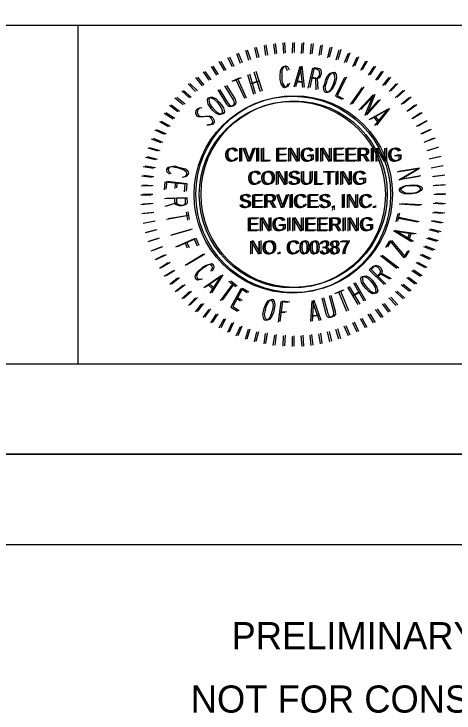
# Model space of a CAD drawing. Extents: x -16 to 5016, y -5 to 5003.
# Drawn here: x 23.858 to 26.289, y -3.799 to 0.062 of the extents above; entities that cross this region are included whole.
import ezdxf

# ---------------------------------------------------------------- set-up
doc = ezdxf.new("R2010")
doc.units = 0
for name, color, linetype in [('Level 8', 7, 'Continuous'), ('RD_SHT_Bndy', 7, 'Continuous'), ('RD_SHT_IplotShp', 7, 'Continuous'), ('RD_SHT_Misc1', 7, 'Continuous'), ('RD_SHT_SEAL_DR', 7, 'Continuous'), ('RD_SHT_SEAL_MA', 7, 'Continuous'), ('RD_SHT_Snap', 7, 'Continuous'), ('RD_SHT_TX', 7, 'Continuous')]:
    doc.layers.add(name, color=color, linetype=linetype)

msp = doc.modelspace()

# ---------------------------------------------------------------- linework, layer by layer
at = {"layer": 'RD_SHT_Bndy'}
for p, q in [((0, -1.87), (33.5, -1.87)), ((33.771, -2.37), (-1.429, -2.37)), ((33.77, -2.871), (-1.43, -2.87))]:
    msp.add_line(p, q, dxfattribs=at)
at = {"layer": 'RD_SHT_IplotShp'}
msp.add_lwpolyline([(-2.129, 19.63), (33.871, 19.63), (33.871, -2.37), (-2.129, -2.37)], close=True, dxfattribs=at)
at = {"layer": 'RD_SHT_Misc1'}
msp.add_lwpolyline([(33.7703, -2.37), (33.771, 19.63), (-0.229, 19.631), (-0.2297, -2.369)], close=True, dxfattribs=at)
at = {"layer": 'RD_SHT_SEAL_DR'}
for p, q in [((25.2492, -0.1087), (25.2582, -0.1647)), ((25.3012, -0.1017), (25.3082, -0.1567)), ((25.3532, -0.0947), (25.3562, -0.1527)), ((25.4062, -0.0947), (25.4052, -0.1507)), ((25.4582, -0.0957), (25.4542, -0.1537)), ((25.5102, -0.1007), (25.5032, -0.1577)), ((25.5612, -0.1087), (25.5522, -0.1637)), ((25.0972, -0.1527), (25.1182, -0.2067)), ((25.1462, -0.1357), (25.1642, -0.1897)), ((25.1962, -0.1207), (25.2102, -0.1767)), ((25.6132, -0.1207), (25.5992, -0.1767)), ((25.6632, -0.1347), (25.6462, -0.1907)), ((25.7132, -0.1527), (25.6922, -0.2057)), ((25.0482, -0.1747), (25.0732, -0.2257)), ((25.7612, -0.1747), (25.7382, -0.2267)), ((24.9572, -0.2257), (24.9862, -0.2727)), ((25.0002, -0.1977), (25.0292, -0.2477)), ((25.8092, -0.1977), (25.7812, -0.2467)), ((25.8552, -0.2257), (25.8242, -0.2737)), ((24.9122, -0.2547), (24.9452, -0.3007)), ((25.8972, -0.2537), (25.8642, -0.3007)), ((24.8712, -0.2867), (24.9072, -0.3317)), ((25.9382, -0.2867), (25.9042, -0.3307)), ((24.8302, -0.3217), (24.8712, -0.3627)), ((25.9792, -0.3217), (25.9402, -0.3627)), ((24.7952, -0.3597), (24.8372, -0.3977)), ((26.0172, -0.3587), (25.9742, -0.3977)), ((24.7572, -0.3977), (24.8032, -0.4347)), ((26.0512, -0.3977), (26.0072, -0.4347)), ((24.7272, -0.4397), (24.7732, -0.4747)), ((26.0832, -0.4397), (26.0372, -0.4737)), ((24.6972, -0.4827), (24.7472, -0.5137)), ((26.1132, -0.4837), (26.0652, -0.5137)), ((24.6712, -0.5297), (24.7202, -0.5567)), ((26.1412, -0.5287), (26.0902, -0.5567)), ((24.6462, -0.5757), (24.6982, -0.5997)), ((26.1622, -0.5757), (26.1132, -0.5997)), ((24.6262, -0.6247), (24.6792, -0.6457)), ((26.1842, -0.6237), (26.1312, -0.6447)), ((24.6072, -0.6747), (24.6632, -0.6917)), ((26.2032, -0.6737), (26.1482, -0.6917)), ((24.5942, -0.7257), (24.6492, -0.7397)), ((26.2172, -0.7247), (26.1612, -0.7377)), ((24.5822, -0.7767), (24.6392, -0.7867)), ((26.2282, -0.7757), (26.1722, -0.7877)), ((24.5732, -0.8287), (24.6312, -0.8357)), ((26.2382, -0.8277), (26.1792, -0.8347)), ((24.5702, -0.8817), (24.6262, -0.8847)), ((26.2422, -0.8807), (26.1842, -0.8847)), ((24.5692, -0.9337), (24.6252, -0.9337)), ((26.2432, -0.9337), (26.1872, -0.9327)), ((24.5692, -0.9867), (24.6262, -0.9827)), ((26.2422, -0.9857), (26.1842, -0.9817)), ((24.5742, -1.0377), (24.6312, -1.0317)), ((26.2372, -1.0377), (26.1792, -1.0327)), ((24.5812, -1.0907), (24.6372, -1.0797)), ((26.2282, -1.0907), (26.1722, -1.0797)), ((24.5942, -1.1427), (24.6482, -1.1277)), ((26.2172, -1.1417), (26.1612, -1.1267)), ((24.6092, -1.1917), (24.6622, -1.1747)), ((26.2032, -1.1917), (26.1482, -1.1747)), ((24.6262, -1.2427), (24.6802, -1.2217)), ((26.1842, -1.2407), (26.1312, -1.2207)), ((24.6472, -1.2917), (24.7002, -1.2657)), ((26.1632, -1.2907), (26.1122, -1.2657)), ((24.6712, -1.3387), (24.7202, -1.3087)), ((26.1402, -1.3377), (26.0892, -1.3097)), ((24.6982, -1.3827), (24.7462, -1.3537)), ((26.1132, -1.3847), (26.0652, -1.3537)), ((24.7282, -1.4277), (24.7722, -1.3927)), ((26.0832, -1.4277), (26.0372, -1.3927)), ((24.7582, -1.4677), (24.8032, -1.4327)), ((26.0522, -1.4677), (26.0072, -1.4317)), ((24.7952, -1.5077), (24.8382, -1.4687)), ((24.8322, -1.5447), (24.8712, -1.5037)), ((25.9792, -1.5447), (25.9392, -1.5027)), ((26.0172, -1.5077), (25.9752, -1.4687)), ((24.8712, -1.5807), (24.9062, -1.5367)), ((25.9382, -1.5817), (25.9042, -1.5367)), ((24.9132, -1.6117), (24.9462, -1.5667)), ((25.8982, -1.6117), (25.8652, -1.5667)), ((24.9552, -1.6417), (24.9862, -1.5937)), ((25.0022, -1.6687), (25.0292, -1.6197)), ((25.8092, -1.6687), (25.7812, -1.6197)), ((25.8542, -1.6417), (25.8252, -1.5937)), ((25.0492, -1.6927), (25.0732, -1.6407)), ((25.7152, -1.7127), (25.6922, -1.6597)), ((25.7632, -1.6917), (25.7392, -1.6407)), ((25.0962, -1.7137), (25.1192, -1.6607)), ((25.1462, -1.7317), (25.1632, -1.6767)), ((25.1962, -1.7457), (25.2102, -1.6907)), ((25.6132, -1.7457), (25.6002, -1.6907)), ((25.6632, -1.7317), (25.6462, -1.6777)), ((25.2492, -1.7577), (25.2582, -1.6997)), ((25.3002, -1.7667), (25.3082, -1.7087)), ((25.3542, -1.7707), (25.3572, -1.7127)), ((25.4062, -1.7717), (25.4062, -1.7157)), ((25.4592, -1.7717), (25.4552, -1.7127)), ((25.5102, -1.7667), (25.5032, -1.7087)), ((25.5612, -1.7577), (25.5522, -1.7017))]:
    msp.add_line(p, q, dxfattribs=at)
for points in [[(25.3792, -0.2487), (25.3702, -0.2297), (25.3612, -0.2267), (25.3562, -0.2267), (25.3472, -0.2307), (25.3382, -0.2497), (25.3372, -0.2757), (25.3372, -0.2887), (25.3372, -0.2977), (25.3382, -0.3047), (25.3412, -0.3207), (25.3522, -0.3377), (25.3602, -0.3407), (25.3642, -0.3407), (25.3732, -0.3367), (25.3822, -0.3187)], [(25.4152, -0.3377), (25.4482, -0.2257), (25.4612, -0.3417)], [(25.1582, -0.2687), (25.1912, -0.3777)], [(25.2302, -0.3647), (25.1952, -0.2557)], [(25.4932, -0.3447), (25.5182, -0.2337), (25.5452, -0.2397), (25.5522, -0.2457), (25.5552, -0.2637), (25.5532, -0.2757), (25.5432, -0.2917), (25.5342, -0.2937), (25.5052, -0.2887)], [(25.6262, -0.2597), (25.6312, -0.2617), (25.6372, -0.2717), (25.6402, -0.2927), (25.6342, -0.3137), (25.6272, -0.3337), (25.6162, -0.3537), (25.6012, -0.3687), (25.5912, -0.3697), (25.5872, -0.3677), (25.5812, -0.3607), (25.5772, -0.3397), (25.5842, -0.3187), (25.5902, -0.2977), (25.6002, -0.2777), (25.6152, -0.2617), (25.6262, -0.2597)], [(25.0732, -0.3067), (25.1142, -0.2887)], [(25.0942, -0.2977), (25.1412, -0.4007)], [(25.2122, -0.3087), (25.1752, -0.3217)], [(25.5332, -0.2937), (25.5362, -0.3537)], [(25.6942, -0.2867), (25.6432, -0.3887), (25.6782, -0.4057)], [(24.9932, -0.3547), (25.0412, -0.4327), (25.0522, -0.4447), (25.0662, -0.4457), (25.0822, -0.4367), (25.0852, -0.4257), (25.0812, -0.4087), (25.0332, -0.3327)], [(25.4592, -0.3137), (25.4222, -0.3097)], [(25.7272, -0.4347), (25.7932, -0.3407)], [(25.7732, -0.4657), (25.8512, -0.3817), (25.8062, -0.4957), (25.8822, -0.4107)], [(24.9392, -0.4007), (24.9432, -0.3977), (24.9542, -0.3967), (24.9742, -0.4057), (24.9902, -0.4227), (25.0022, -0.4377), (25.0152, -0.4567), (25.0202, -0.4777), (25.0152, -0.4867), (25.0112, -0.4897), (25.0022, -0.4917), (24.9832, -0.4837), (24.9672, -0.4687), (24.9532, -0.4517), (24.9402, -0.4327), (24.9362, -0.4107), (24.9392, -0.4007)], [(24.8952, -0.4557), (24.8812, -0.4587), (24.8722, -0.4687), (24.8702, -0.4827), (24.8762, -0.4957), (24.8812, -0.4997), (24.8952, -0.5037), (24.9362, -0.4997), (24.9492, -0.5037), (24.9572, -0.5117), (24.9642, -0.5267), (24.9632, -0.5377), (24.9542, -0.5477), (24.9462, -0.5497), (24.9342, -0.5487)], [(25.8302, -0.5177), (25.9322, -0.4607), (25.8602, -0.5517)], [(25.8772, -0.5307), (25.8552, -0.5037)], [(24.7962, -0.8367), (24.8152, -0.8327), (24.8212, -0.8247), (24.8232, -0.8187), (24.8212, -0.8087), (24.8052, -0.7957), (24.7822, -0.7887), (24.7672, -0.7857), (24.7582, -0.7827), (24.7522, -0.7807), (24.7372, -0.7797), (24.7172, -0.7837), (24.7112, -0.7917), (24.7102, -0.7967), (24.7112, -0.8057), (24.7272, -0.8207)], [(26.1052, -0.8327), (25.9932, -0.8517), (26.0982, -0.7897), (25.9842, -0.8087)], [(24.8102, -0.9167), (24.8142, -0.8757), (24.7022, -0.8637), (24.6972, -0.9057)], [(24.7582, -0.8707), (24.7562, -0.8987)], [(25.9972, -0.9107), (25.9972, -0.9047), (26.0032, -0.8957), (26.0222, -0.8857), (26.0432, -0.8827), (26.0652, -0.8817), (26.0872, -0.8827), (26.1062, -0.8907), (26.1122, -0.8987), (26.1122, -0.9037), (26.1072, -0.9127), (26.0892, -0.9247), (26.0662, -0.9277), (26.0462, -0.9287), (26.0232, -0.9277), (26.0042, -0.9187), (25.9972, -0.9107)], [(24.7002, -0.9547), (24.8132, -0.9507), (24.8142, -0.9807), (24.8102, -0.9887), (24.7932, -0.9957), (24.7822, -0.9957), (24.7632, -0.9897), (24.7572, -0.9817), (24.7572, -0.9537)], [(24.7572, -0.9817), (24.7012, -0.9987)], [(26.1112, -0.9927), (25.9962, -0.9857)], [(24.8192, -1.0297), (24.8262, -1.0737)], [(25.9792, -1.0827), (25.9892, -1.0377)], [(24.8232, -1.0507), (24.7102, -1.0697)], [(25.9842, -1.0607), (26.0962, -1.0837)], [(24.7342, -1.1567), (24.8442, -1.1247)], [(26.0642, -1.1937), (25.9642, -1.1337), (26.0792, -1.1497)], [(26.0522, -1.1467), (26.0402, -1.1797)], [(24.8812, -1.2167), (24.8642, -1.1777), (24.7602, -1.2237)], [(25.9222, -1.2247), (25.9432, -1.1887), (26.0212, -1.2817), (26.0432, -1.2437)], [(24.8132, -1.2007), (24.8252, -1.2277)], [(24.8132, -1.3217), (24.9122, -1.2627)], [(25.9832, -1.3417), (25.8922, -1.2717)], [(24.9552, -1.3557), (24.9642, -1.3377), (24.9622, -1.3277), (24.9582, -1.3237), (24.9502, -1.3187), (24.9302, -1.3237), (24.9082, -1.3377), (24.8982, -1.3457), (24.8902, -1.3517), (24.8852, -1.3557), (24.8742, -1.3677), (24.8662, -1.3857), (24.8692, -1.3947), (24.8722, -1.3987), (24.8812, -1.4027), (24.9002, -1.4007)], [(25.9122, -1.4297), (25.8302, -1.3487), (25.8512, -1.3287), (25.8592, -1.3257), (25.8772, -1.3327), (25.8842, -1.3407), (25.8922, -1.3577), (25.8892, -1.3687), (25.8702, -1.3877)], [(24.9162, -1.4457), (25.0122, -1.3787), (24.9492, -1.4777)], [(25.7862, -1.3887), (25.7922, -1.3857), (25.8032, -1.3847), (25.8222, -1.3937), (25.8372, -1.4087), (25.8512, -1.4277), (25.8622, -1.4467), (25.8672, -1.4667), (25.8622, -1.4757), (25.8582, -1.4797), (25.8482, -1.4807), (25.8292, -1.4707), (25.8142, -1.4537), (25.8012, -1.4387), (25.7872, -1.4187), (25.7842, -1.3987), (25.7862, -1.3887)], [(25.8882, -1.3687), (25.9422, -1.3987)], [(25.0742, -1.4267), (25.0072, -1.5187)], [(25.0552, -1.4117), (25.0912, -1.4397)], [(25.8022, -1.5217), (25.7452, -1.4227)], [(24.9642, -1.4527), (24.9382, -1.4297)], [(25.1562, -1.4747), (25.1212, -1.4537), (25.0662, -1.5537), (25.1022, -1.5757)], [(25.6402, -1.4787), (25.6822, -1.4607)], [(25.7102, -1.4437), (25.7682, -1.5407)], [(25.0932, -1.5037), (25.1192, -1.5187)], [(25.5682, -1.5047), (25.5912, -1.5917), (25.5982, -1.6067), (25.6092, -1.6117), (25.6282, -1.6057), (25.6352, -1.5967), (25.6342, -1.5817), (25.6102, -1.4927)], [(25.6612, -1.4697), (25.7052, -1.5757)], [(25.7732, -1.4717), (25.7392, -1.4917)], [(25.2822, -1.5137), (25.2882, -1.5157), (25.2962, -1.5247), (25.2992, -1.5437), (25.2962, -1.5677), (25.2912, -1.5867), (25.2822, -1.6077), (25.2692, -1.6257), (25.2602, -1.6277), (25.2542, -1.6267), (25.2482, -1.6197), (25.2422, -1.5977), (25.2472, -1.5757), (25.2512, -1.5557), (25.2602, -1.5347), (25.2722, -1.5187), (25.2822, -1.5137)], [(25.3812, -1.5287), (25.3422, -1.5247), (25.3272, -1.6367)], [(25.5072, -1.6337), (25.5152, -1.5187), (25.5532, -1.6287)], [(25.3352, -1.5807), (25.3632, -1.5837)], [(25.5442, -1.6017), (25.5102, -1.6057)]]:
    msp.add_lwpolyline(points, dxfattribs=at)
for major_axis in [(0, 0.5436), (0, 0.515)]:
    msp.add_ellipse((25.4055, -0.9331), major_axis=major_axis, ratio=0.998589, dxfattribs=at)
at = {"layer": 'RD_SHT_SEAL_MA'}
for p, q in [((25.2393, -0.1114), (25.2483, -0.1674)), ((25.2913, -0.1044), (25.2983, -0.1594)), ((25.3433, -0.0974), (25.3463, -0.1554)), ((25.3963, -0.0974), (25.3953, -0.1534)), ((25.4483, -0.0984), (25.4443, -0.1564)), ((25.5003, -0.1034), (25.4933, -0.1604)), ((25.5513, -0.1114), (25.5423, -0.1664)), ((25.1363, -0.1384), (25.1543, -0.1924)), ((25.1863, -0.1234), (25.2003, -0.1794)), ((25.6033, -0.1234), (25.5893, -0.1794)), ((25.6533, -0.1374), (25.6363, -0.1934)), ((25.0383, -0.1774), (25.0633, -0.2284)), ((25.0873, -0.1554), (25.1083, -0.2094)), ((25.7033, -0.1554), (25.6823, -0.2084)), ((25.7513, -0.1774), (25.7283, -0.2294)), ((24.9473, -0.2284), (24.9763, -0.2754)), ((24.9903, -0.2004), (25.0193, -0.2504)), ((25.7993, -0.2004), (25.7713, -0.2494)), ((25.8453, -0.2284), (25.8143, -0.2764)), ((24.9023, -0.2574), (24.9353, -0.3034)), ((25.8873, -0.2564), (25.8543, -0.3034)), ((24.8613, -0.2894), (24.8973, -0.3344)), ((25.9283, -0.2894), (25.8943, -0.3334)), ((24.8203, -0.3244), (24.8613, -0.3654)), ((25.9693, -0.3244), (25.9303, -0.3654)), ((24.7853, -0.3624), (24.8273, -0.4004)), ((26.0073, -0.3614), (25.9643, -0.4004)), ((24.7473, -0.4004), (24.7933, -0.4374)), ((26.0413, -0.4004), (25.9973, -0.4374)), ((24.7173, -0.4424), (24.7633, -0.4774)), ((26.0733, -0.4424), (26.0273, -0.4764)), ((24.6873, -0.4854), (24.7373, -0.5164)), ((26.1033, -0.4864), (26.0553, -0.5164)), ((24.6613, -0.5324), (24.7103, -0.5594)), ((26.1313, -0.5314), (26.0803, -0.5594)), ((24.6363, -0.5784), (24.6883, -0.6024)), ((26.1523, -0.5784), (26.1033, -0.6024)), ((24.6163, -0.6274), (24.6693, -0.6484)), ((26.1743, -0.6264), (26.1213, -0.6474)), ((24.5973, -0.6774), (24.6533, -0.6944)), ((26.1933, -0.6764), (26.1383, -0.6944)), ((24.5843, -0.7284), (24.6393, -0.7424)), ((26.2073, -0.7274), (26.1513, -0.7404)), ((24.5723, -0.7794), (24.6293, -0.7894)), ((26.2183, -0.7784), (26.1623, -0.7904)), ((24.5633, -0.8314), (24.6213, -0.8384)), ((26.2283, -0.8304), (26.1693, -0.8374)), ((24.5603, -0.8844), (24.6163, -0.8874)), ((26.2323, -0.8834), (26.1743, -0.8874)), ((24.5593, -0.9364), (24.6153, -0.9364)), ((26.2333, -0.9364), (26.1773, -0.9354)), ((24.5593, -0.9894), (24.6163, -0.9854)), ((26.2323, -0.9884), (26.1743, -0.9844)), ((24.5643, -1.0404), (24.6213, -1.0344)), ((26.2273, -1.0404), (26.1693, -1.0354)), ((24.5713, -1.0934), (24.6273, -1.0824)), ((26.2183, -1.0934), (26.1623, -1.0824)), ((24.5843, -1.1454), (24.6383, -1.1304)), ((26.2073, -1.1444), (26.1513, -1.1294)), ((24.5993, -1.1944), (24.6523, -1.1774)), ((26.1933, -1.1944), (26.1383, -1.1774)), ((24.6163, -1.2454), (24.6703, -1.2244)), ((26.1743, -1.2434), (26.1213, -1.2234)), ((24.6373, -1.2944), (24.6903, -1.2684)), ((26.1533, -1.2934), (26.1023, -1.2684)), ((24.6613, -1.3414), (24.7103, -1.3114)), ((26.1303, -1.3404), (26.0793, -1.3124)), ((24.6883, -1.3854), (24.7363, -1.3564)), ((26.1033, -1.3874), (26.0553, -1.3564)), ((24.7183, -1.4304), (24.7623, -1.3954)), ((26.0733, -1.4304), (26.0273, -1.3954)), ((24.7483, -1.4704), (24.7933, -1.4354)), ((26.0423, -1.4704), (25.9973, -1.4344)), ((24.7853, -1.5104), (24.8283, -1.4714)), ((25.9693, -1.5474), (25.9293, -1.5054)), ((26.0073, -1.5104), (25.9653, -1.4714)), ((24.8223, -1.5474), (24.8613, -1.5064)), ((24.8613, -1.5834), (24.8963, -1.5394)), ((25.9283, -1.5844), (25.8943, -1.5394)), ((24.9033, -1.6144), (24.9363, -1.5694)), ((25.8883, -1.6144), (25.8553, -1.5694)), ((24.9453, -1.6444), (24.9763, -1.5964)), ((25.8443, -1.6444), (25.8153, -1.5964)), ((24.9923, -1.6714), (25.0193, -1.6224)), ((25.0393, -1.6954), (25.0633, -1.6434)), ((25.7533, -1.6944), (25.7293, -1.6434)), ((25.7993, -1.6714), (25.7713, -1.6224)), ((25.0863, -1.7164), (25.1093, -1.6634)), ((25.1363, -1.7344), (25.1533, -1.6794)), ((25.1863, -1.7484), (25.2003, -1.6934)), ((25.6033, -1.7484), (25.5903, -1.6934)), ((25.6533, -1.7344), (25.6363, -1.6804)), ((25.7053, -1.7154), (25.6823, -1.6624)), ((25.2393, -1.7604), (25.2483, -1.7024)), ((25.2903, -1.7694), (25.2983, -1.7114)), ((25.3443, -1.7734), (25.3473, -1.7154)), ((25.3963, -1.7744), (25.3963, -1.7184)), ((25.4493, -1.7744), (25.4453, -1.7154)), ((25.5003, -1.7694), (25.4933, -1.7114)), ((25.5513, -1.7604), (25.5423, -1.7044))]:
    msp.add_line(p, q, dxfattribs=at)
for points in [[(25.3693, -0.2514), (25.3603, -0.2324), (25.3513, -0.2294), (25.3463, -0.2294), (25.3373, -0.2334), (25.3283, -0.2524), (25.3273, -0.2784), (25.3273, -0.2914), (25.3273, -0.3004), (25.3283, -0.3074), (25.3313, -0.3234), (25.3423, -0.3404), (25.3503, -0.3434), (25.3543, -0.3434), (25.3633, -0.3394), (25.3723, -0.3214)], [(25.4053, -0.3404), (25.4383, -0.2284), (25.4513, -0.3444)], [(25.2203, -0.3674), (25.1853, -0.2584)], [(25.4833, -0.3474), (25.5083, -0.2364), (25.5353, -0.2424), (25.5423, -0.2484), (25.5453, -0.2664), (25.5433, -0.2784), (25.5333, -0.2944), (25.5243, -0.2964), (25.4953, -0.2914)], [(25.6163, -0.2624), (25.6213, -0.2644), (25.6273, -0.2744), (25.6303, -0.2954), (25.6243, -0.3164), (25.6173, -0.3364), (25.6063, -0.3564), (25.5913, -0.3714), (25.5813, -0.3724), (25.5773, -0.3704), (25.5713, -0.3634), (25.5673, -0.3424), (25.5743, -0.3214), (25.5803, -0.3004), (25.5903, -0.2804), (25.6053, -0.2644), (25.6163, -0.2624)], [(25.0633, -0.3094), (25.1043, -0.2914)], [(25.0843, -0.3004), (25.1313, -0.4034)], [(25.1483, -0.2714), (25.1813, -0.3804)], [(25.5233, -0.2964), (25.5263, -0.3564)], [(25.6843, -0.2894), (25.6333, -0.3914), (25.6683, -0.4084)], [(24.9833, -0.3574), (25.0313, -0.4354), (25.0423, -0.4474), (25.0563, -0.4484), (25.0723, -0.4394), (25.0753, -0.4284), (25.0713, -0.4114), (25.0233, -0.3354)], [(25.2023, -0.3114), (25.1653, -0.3244)], [(25.4493, -0.3164), (25.4123, -0.3124)], [(25.7173, -0.4374), (25.7833, -0.3434)], [(25.7633, -0.4684), (25.8413, -0.3844), (25.7963, -0.4984), (25.8723, -0.4134)], [(24.9293, -0.4034), (24.9333, -0.4004), (24.9443, -0.3994), (24.9643, -0.4084), (24.9803, -0.4254), (24.9923, -0.4404), (25.0053, -0.4594), (25.0103, -0.4804), (25.0053, -0.4894), (25.0013, -0.4924), (24.9923, -0.4944), (24.9733, -0.4864), (24.9573, -0.4714), (24.9433, -0.4544), (24.9303, -0.4354), (24.9263, -0.4134), (24.9293, -0.4034)], [(24.8853, -0.4584), (24.8713, -0.4614), (24.8623, -0.4714), (24.8603, -0.4854), (24.8663, -0.4984), (24.8713, -0.5024), (24.8853, -0.5064), (24.9263, -0.5024), (24.9393, -0.5064), (24.9473, -0.5144), (24.9543, -0.5294), (24.9533, -0.5404), (24.9443, -0.5504), (24.9363, -0.5524), (24.9243, -0.5514)], [(25.8203, -0.5204), (25.9223, -0.4634), (25.8503, -0.5544)], [(25.8673, -0.5334), (25.8453, -0.5064)], [(24.7863, -0.8394), (24.8053, -0.8354), (24.8113, -0.8274), (24.8133, -0.8214), (24.8113, -0.8114), (24.7953, -0.7984), (24.7723, -0.7914), (24.7573, -0.7884), (24.7483, -0.7854), (24.7423, -0.7834), (24.7273, -0.7824), (24.7073, -0.7864), (24.7013, -0.7944), (24.7003, -0.7994), (24.7013, -0.8084), (24.7173, -0.8234)], [(26.0953, -0.8354), (25.9833, -0.8544), (26.0883, -0.7924), (25.9743, -0.8114)], [(24.8003, -0.9194), (24.8043, -0.8784), (24.6923, -0.8664), (24.6873, -0.9084)], [(24.7483, -0.8734), (24.7463, -0.9014)], [(25.9873, -0.9134), (25.9873, -0.9074), (25.9933, -0.8984), (26.0123, -0.8884), (26.0333, -0.8854), (26.0553, -0.8844), (26.0773, -0.8854), (26.0963, -0.8934), (26.1023, -0.9014), (26.1023, -0.9064), (26.0973, -0.9154), (26.0793, -0.9274), (26.0563, -0.9304), (26.0363, -0.9314), (26.0133, -0.9304), (25.9943, -0.9214), (25.9873, -0.9134)], [(24.6903, -0.9574), (24.8033, -0.9534), (24.8043, -0.9834), (24.8003, -0.9914), (24.7833, -0.9984), (24.7723, -0.9984), (24.7533, -0.9924), (24.7473, -0.9844), (24.7473, -0.9564)], [(24.7473, -0.9844), (24.6913, -1.0014)], [(26.1013, -0.9954), (25.9863, -0.9884)], [(24.8093, -1.0324), (24.8163, -1.0764)], [(25.9693, -1.0854), (25.9793, -1.0404)], [(24.8133, -1.0534), (24.7003, -1.0724)], [(25.9743, -1.0634), (26.0863, -1.0864)], [(24.7243, -1.1594), (24.8343, -1.1274)], [(26.0543, -1.1964), (25.9543, -1.1364), (26.0693, -1.1524)], [(26.0423, -1.1494), (26.0303, -1.1824)], [(24.8713, -1.2194), (24.8543, -1.1804), (24.7503, -1.2264)], [(25.9123, -1.2274), (25.9333, -1.1914), (26.0113, -1.2844), (26.0333, -1.2464)], [(24.8033, -1.2034), (24.8153, -1.2304)], [(24.8033, -1.3244), (24.9023, -1.2654)], [(25.9733, -1.3444), (25.8823, -1.2744)], [(24.9453, -1.3584), (24.9543, -1.3404), (24.9523, -1.3304), (24.9483, -1.3264), (24.9403, -1.3214), (24.9203, -1.3264), (24.8983, -1.3404), (24.8883, -1.3484), (24.8803, -1.3544), (24.8753, -1.3584), (24.8643, -1.3704), (24.8563, -1.3884), (24.8593, -1.3974), (24.8623, -1.4014), (24.8713, -1.4054), (24.8903, -1.4034)], [(25.9023, -1.4324), (25.8203, -1.3514), (25.8413, -1.3314), (25.8493, -1.3284), (25.8673, -1.3354), (25.8743, -1.3434), (25.8823, -1.3604), (25.8793, -1.3714), (25.8603, -1.3904)], [(24.9063, -1.4484), (25.0023, -1.3814), (24.9393, -1.4804)], [(25.7763, -1.3914), (25.7823, -1.3884), (25.7933, -1.3874), (25.8123, -1.3964), (25.8273, -1.4114), (25.8413, -1.4304), (25.8523, -1.4494), (25.8573, -1.4694), (25.8523, -1.4784), (25.8483, -1.4824), (25.8383, -1.4834), (25.8193, -1.4734), (25.8043, -1.4564), (25.7913, -1.4414), (25.7773, -1.4214), (25.7743, -1.4014), (25.7763, -1.3914)], [(25.8783, -1.3714), (25.9323, -1.4014)], [(25.0453, -1.4144), (25.0813, -1.4424)], [(25.7923, -1.5244), (25.7353, -1.4254)], [(24.9543, -1.4554), (24.9283, -1.4324)], [(25.0643, -1.4294), (24.9973, -1.5214)], [(25.1463, -1.4774), (25.1113, -1.4564), (25.0563, -1.5564), (25.0923, -1.5784)], [(25.6303, -1.4814), (25.6723, -1.4634)], [(25.7003, -1.4464), (25.7583, -1.5434)], [(25.5583, -1.5074), (25.5813, -1.5944), (25.5883, -1.6094), (25.5993, -1.6144), (25.6183, -1.6084), (25.6253, -1.5994), (25.6243, -1.5844), (25.6003, -1.4954)], [(25.6513, -1.4724), (25.6953, -1.5784)], [(25.7633, -1.4744), (25.7293, -1.4944)], [(25.0833, -1.5064), (25.1093, -1.5214)], [(25.2723, -1.5164), (25.2783, -1.5184), (25.2863, -1.5274), (25.2893, -1.5464), (25.2863, -1.5704), (25.2813, -1.5894), (25.2723, -1.6104), (25.2593, -1.6284), (25.2503, -1.6304), (25.2443, -1.6294), (25.2383, -1.6224), (25.2323, -1.6004), (25.2373, -1.5784), (25.2413, -1.5584), (25.2503, -1.5374), (25.2623, -1.5214), (25.2723, -1.5164)], [(25.3713, -1.5314), (25.3323, -1.5274), (25.3173, -1.6394)], [(25.4973, -1.6364), (25.5053, -1.5214), (25.5433, -1.6314)], [(25.3253, -1.5834), (25.3533, -1.5864)], [(25.5343, -1.6044), (25.5003, -1.6084)]]:
    msp.add_lwpolyline(points, dxfattribs=at)
for major_axis in [(0, 0.5436), (0, 0.515)]:
    msp.add_ellipse((25.3956, -0.9358), major_axis=major_axis, ratio=0.998589, dxfattribs=at)
at = {"layer": 'RD_SHT_Snap'}
msp.add_lwpolyline([(-1.899, 19.63), (34.101, 19.63), (34.101, -2.37), (-1.899, -2.37)], close=True, dxfattribs=at)
at = {"layer": 'RD_SHT_TX'}
for p, q in [((0, 0), (33.5, 0)), ((24.2131, -1.87), (24.2131, 0))]:
    msp.add_line(p, q, dxfattribs=at)

# ---------------------------------------------------------------- texts
at = {"layer": 'Level 8'}
for s, p in [('PRELIMINARY PLANS', (25.0598, -3.4466)), ('NOT FOR CONSTRUCTION', (24.8347, -3.7966))]:
    msp.add_text(s, height=0.15, rotation=359.9984, dxfattribs=at).set_placement(p)
at = {"layer": 'RD_SHT_SEAL_DR'}
for s, p in [('CIVIL ENGINEERING', (25.0287, -0.751)), ('CONSULTING', (25.1557, -0.879)), ('SERVICES, INC.', (25.1077, -1.007)), ('ENGINEERING', (25.1507, -1.135)), ('NO. C00387', (25.1627, -1.263))]:
    msp.add_text(s, height=0.07476, rotation=0.0014, dxfattribs=at).set_placement(p)
at = {"layer": 'RD_SHT_SEAL_MA'}
for s, p in [('CIVIL ENGINEERING', (25.0188, -0.7537)), ('CONSULTING', (25.1458, -0.8817)), ('SERVICES, INC.', (25.0978, -1.0097)), ('ENGINEERING', (25.1408, -1.1377)), ('NO. C00387', (25.1528, -1.2657))]:
    msp.add_text(s, height=0.07476, rotation=0.0014, dxfattribs=at).set_placement(p)

doc.saveas('drawing.dxf')
